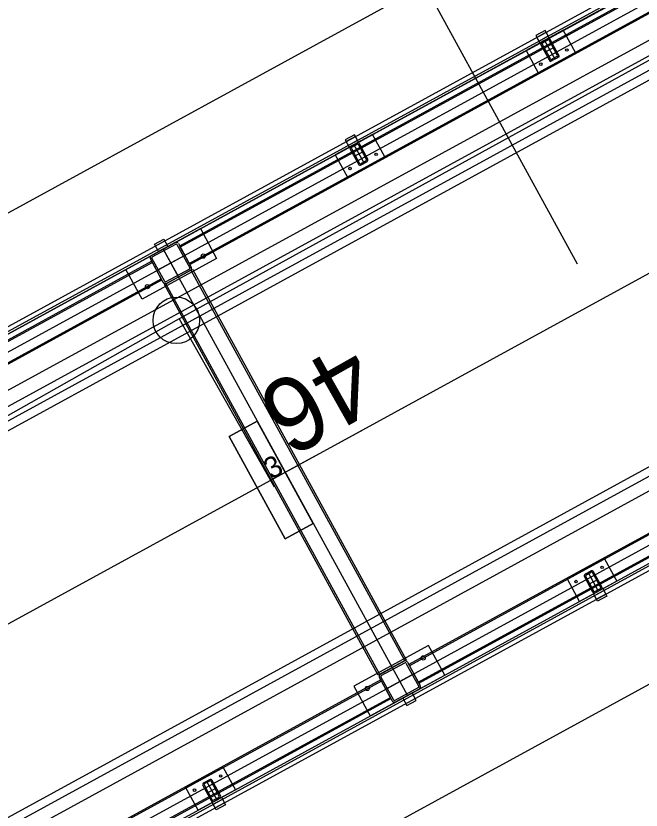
# Model space of a CAD drawing. Extents: x -783978 to -783565, y -1064821 to -1064596.
# Drawn here: x -783784.57 to -783781.623, y -1064693.706 to -1064689.961 of the extents above; entities that cross this region are included whole.
import ezdxf

# ---------------------------------------------------------------- set-up
doc = ezdxf.new("R2010")
doc.units = 0
for name, color, linetype in [('Default', 7, 'Continuous'), ('SO 01_20_01', 7, 'Continuous'), ('SO 01_50_01', 7, 'Continuous'), ('SO 01_74_01', 7, 'Continuous'), ('SO 01_86_04', 7, 'Continuous')]:
    doc.layers.add(name, color=color, linetype=linetype)

# ---------------------------------------------------------------- blocks, each defined once
blk = doc.blocks.new('POINT_DISPLAY')
at = {"layer": 'Default'}
blk.add_line((0, 0), (0, 0), dxfattribs=at)

msp = doc.modelspace()

# ---------------------------------------------------------------- linework, layer by layer
at = {"layer": 'SO 01_20_01'}
for p, q in [((-783735.0054, -1064663.7532), (-783787.4671, -1064692.4555)), ((-783735.2041, -1064664.4318), (-783786.7885, -1064692.6541)), ((-783786.6445, -1064692.9173), (-783735.3233, -1064664.839)), ((-783738.0171, -1064666.3812), (-783786.4402, -1064692.874)), ((-783786.421, -1064692.9091), (-783737.9979, -1064666.4163)), ((-783737.8741, -1064667.2605), (-783785.3352, -1064693.2269)), ((-783785.6531, -1064694.3127), (-783737.23, -1064667.82)), ((-783737.0912, -1064667.858), (-783785.7805, -1064694.4964)), ((-783737.2108, -1064667.855), (-783785.6339, -1064694.3478)), ((-783785.6366, -1064694.7596), (-783736.9472, -1064668.1212)), ((-783746.2961, -1064673.8055), (-783785.8354, -1064695.4379))]:
    msp.add_line(p, q, dxfattribs=at)
at = {"layer": 'SO 01_50_01'}
for p, q in [((-783786.7885, -1064692.6541), (-783725.4827, -1064659.1131)), ((-783782.4021, -1064690.2543), (-783778.0156, -1064687.8544)), ((-783782.402, -1064690.2544), (-783778.0156, -1064687.8545)), ((-783782.402, -1064690.2544), (-783778.0156, -1064687.8545)), ((-783781.9221, -1064691.1316), (-783782.882, -1064689.377)), ((-783786.7885, -1064692.6541), (-783782.4021, -1064690.2543)), ((-783786.7884, -1064692.6542), (-783782.402, -1064690.2544)), ((-783786.7884, -1064692.6542), (-783782.402, -1064690.2544))]:
    msp.add_line(p, q, dxfattribs=at)
at = {"layer": 'SO 01_74_01'}
for p, q in [((-783735.2185, -1064664.4055), (-783786.6099, -1064692.5222)), ((-783786.6003, -1064692.5398), (-783735.2089, -1064664.423)), ((-783785.4388, -1064694.6628), (-783745.8293, -1064672.9921)), ((-783745.8197, -1064673.0096), (-783785.4292, -1064694.6803)), ((-783781.232, -1064689.6427), (-783783.7981, -1064691.0466)), ((-783781.229, -1064689.6482), (-783783.7951, -1064691.0521)), ((-783783.7531, -1064691.1288), (-783781.1871, -1064689.7249)), ((-783783.7501, -1064691.1343), (-783781.1841, -1064689.7304)), ((-783782.0747, -1064690.0296), (-783782.1186, -1064690.0536)), ((-783782.0555, -1064690.0647), (-783782.0747, -1064690.0296)), ((-783782.1186, -1064690.0536), (-783782.0994, -1064690.0887)), ((-783782.0699, -1064690.0384), (-783782.1138, -1064690.0624)), ((-783782.1138, -1064690.0624), (-783782.1042, -1064690.0799)), ((-783782.1042, -1064690.0799), (-783782.0603, -1064690.0559)), ((-783782.0994, -1064690.0887), (-783782.0555, -1064690.0647)), ((-783782.0603, -1064690.0559), (-783782.0699, -1064690.0384)), ((-783782.974, -1064690.5216), (-783783.0178, -1064690.5456)), ((-783782.9548, -1064690.5567), (-783782.974, -1064690.5216)), ((-783783.0178, -1064690.5456), (-783782.9986, -1064690.5807)), ((-783782.9692, -1064690.5303), (-783783.013, -1064690.5543)), ((-783783.013, -1064690.5543), (-783783.0034, -1064690.5719)), ((-783783.0034, -1064690.5719), (-783782.9596, -1064690.5479)), ((-783782.9986, -1064690.5807), (-783782.9548, -1064690.5567)), ((-783782.9596, -1064690.5479), (-783782.9692, -1064690.5303)), ((-783783.917, -1064691.0375), (-783783.8732, -1064691.0135)), ((-783783.8978, -1064691.0726), (-783783.917, -1064691.0375)), ((-783783.8732, -1064691.0135), (-783783.854, -1064691.0486)), ((-783783.7981, -1064691.0466), (-783783.7501, -1064691.1343)), ((-783783.854, -1064691.0486), (-783783.8978, -1064691.0726)), ((-783783.7951, -1064691.0521), (-783783.7531, -1064691.1288)), ((-783783.9297, -1064691.1186), (-783786.4958, -1064692.5225)), ((-783783.8817, -1064691.2063), (-783783.9297, -1064691.1186)), ((-783783.9267, -1064691.1241), (-783786.4927, -1064692.528)), ((-783783.8847, -1064691.2008), (-783783.9267, -1064691.1241)), ((-783783.8697, -1064691.2282), (-783783.7381, -1064691.1562)), ((-783783.7381, -1064691.1562), (-783782.7302, -1064692.9985)), ((-783783.8627, -1064691.2244), (-783783.7451, -1064691.1601)), ((-783783.7451, -1064691.1601), (-783782.7372, -1064693.0024)), ((-783786.4508, -1064692.6047), (-783783.8847, -1064691.2008)), ((-783786.4478, -1064692.6102), (-783783.8817, -1064691.2063)), ((-783782.8618, -1064693.0705), (-783783.8697, -1064691.2282)), ((-783782.8547, -1064693.0667), (-783783.8627, -1064691.2244)), ((-783780.1521, -1064691.6165), (-783782.7182, -1064693.0205)), ((-783780.1491, -1064691.6221), (-783782.7151, -1064693.026)), ((-783782.6732, -1064693.1027), (-783780.1071, -1064691.6987)), ((-783782.6702, -1064693.1082), (-783780.1041, -1064691.7043)), ((-783781.8467, -1064692.6861), (-783781.8028, -1064692.6621)), ((-783781.8275, -1064692.7212), (-783781.8467, -1064692.6861)), ((-783781.8419, -1064692.6949), (-783781.798, -1064692.6709)), ((-783781.7884, -1064692.6885), (-783781.8323, -1064692.7125)), ((-783781.8028, -1064692.6621), (-783781.7836, -1064692.6972)), ((-783781.798, -1064692.6709), (-783781.7884, -1064692.6885)), ((-783781.8323, -1064692.7125), (-783781.8419, -1064692.6949)), ((-783781.7836, -1064692.6972), (-783781.8275, -1064692.7212)), ((-783782.7302, -1064692.9985), (-783782.8618, -1064693.0705)), ((-783782.7372, -1064693.0024), (-783782.8547, -1064693.0667)), ((-783782.7182, -1064693.0205), (-783782.6702, -1064693.1082)), ((-783782.7151, -1064693.026), (-783782.6732, -1064693.1027)), ((-783782.8498, -1064693.0925), (-783785.4158, -1064694.4964)), ((-783782.8467, -1064693.098), (-783785.4128, -1064694.5019)), ((-783782.8018, -1064693.1802), (-783782.8498, -1064693.0925)), ((-783782.8048, -1064693.1747), (-783782.8467, -1064693.098)), ((-783785.3708, -1064694.5786), (-783782.8048, -1064693.1747)), ((-783785.3678, -1064694.5841), (-783782.8018, -1064693.1802)), ((-783782.702, -1064693.1541), (-783782.7459, -1064693.1781)), ((-783782.7459, -1064693.1781), (-783782.7267, -1064693.2132)), ((-783782.6828, -1064693.1892), (-783782.702, -1064693.1541)), ((-783782.7267, -1064693.2132), (-783782.6828, -1064693.1892)), ((-783783.6451, -1064693.6701), (-783783.6013, -1064693.6461)), ((-783783.6403, -1064693.6789), (-783783.5965, -1064693.6549)), ((-783783.6013, -1064693.6461), (-783783.5821, -1064693.6812)), ((-783783.5965, -1064693.6549), (-783783.5869, -1064693.6724)), ((-783783.6259, -1064693.7052), (-783783.6451, -1064693.6701)), ((-783783.6307, -1064693.6964), (-783783.6403, -1064693.6789)), ((-783783.5869, -1064693.6724), (-783783.6307, -1064693.6964)), ((-783783.5821, -1064693.6812), (-783783.6259, -1064693.7052))]:
    msp.add_line(p, q, dxfattribs=at)
for points in [[(-783735.1681, -1064664.4976), (-783787.4762, -1064693.1159)], [(-783734.0882, -1064666.4715), (-783786.3963, -1064695.0898)], [(-783782.0638, -1064690.0692), (-783782.0911, -1064690.0842)], [(-783782.0949, -1064690.097), (-783782.0559, -1064690.1681)], [(-783782.0893, -1064690.094), (-783782.0504, -1064690.1651)], [(-783782.0608, -1064690.0748), (-783782.0881, -1064690.0897)], [(-783782.0775, -1064690.0767), (-783782.0295, -1064690.1644)], [(-783782.0315, -1064690.1086), (-783782.0754, -1064690.1326)], [(-783782.0176, -1064690.1472), (-783782.0565, -1064690.076)], [(-783782.0121, -1064690.1441), (-783782.051, -1064690.073)], [(-783782.0461, -1064690.1664), (-783782.0189, -1064690.1514)], [(-783782.0431, -1064690.1719), (-783782.0158, -1064690.157)], [(-783782.9941, -1064690.589), (-783782.9552, -1064690.6601)], [(-783782.963, -1064690.5612), (-783782.9903, -1064690.5761)], [(-783782.9886, -1064690.5859), (-783782.9496, -1064690.6571)], [(-783782.96, -1064690.5667), (-783782.9873, -1064690.5817)], [(-783782.9767, -1064690.5687), (-783782.9287, -1064690.6564)], [(-783782.9168, -1064690.6391), (-783782.9557, -1064690.568)], [(-783782.9113, -1064690.6361), (-783782.9502, -1064690.565)], [(-783782.9308, -1064690.6005), (-783782.9746, -1064690.6245)], [(-783782.9454, -1064690.6583), (-783782.9181, -1064690.6434)], [(-783782.9423, -1064690.6639), (-783782.915, -1064690.6489)], [(-783783.9312, -1064691.0909), (-783783.8206, -1064691.0304)], [(-783783.9273, -1064691.0979), (-783783.8168, -1064691.0374)], [(-783783.8114, -1064691.039), (-783783.7509, -1064691.1495)], [(-783783.8043, -1064691.0352), (-783783.7439, -1064691.1457)], [(-783783.8759, -1064691.0606), (-783782.724, -1064693.1661)], [(-783783.8759, -1064691.0606), (-783783.8039, -1064691.1922)], [(-783783.8755, -1064691.2177), (-783783.9359, -1064691.1072)], [(-783783.8684, -1064691.2139), (-783783.9289, -1064691.1033)], [(-783783.7741, -1064691.0904), (-783783.9057, -1064691.1624)], [(-783783.7525, -1064691.155), (-783783.863, -1064691.2154)], [(-783783.7486, -1064691.162), (-783783.8592, -1064691.2225)], [(-783781.8591, -1064692.579), (-783781.8864, -1064692.5939)], [(-783781.8901, -1064692.6067), (-783781.8512, -1064692.6779)], [(-783781.8846, -1064692.6037), (-783781.8457, -1064692.6748)], [(-783781.8561, -1064692.5845), (-783781.8834, -1064692.5994)], [(-783781.8728, -1064692.5864), (-783781.8248, -1064692.6741)], [(-783781.8268, -1064692.6183), (-783781.8707, -1064692.6423)], [(-783781.8129, -1064692.6569), (-783781.8518, -1064692.5857)], [(-783781.8074, -1064692.6539), (-783781.8463, -1064692.5827)], [(-783781.8414, -1064692.6761), (-783781.8141, -1064692.6612)], [(-783781.8384, -1064692.6816), (-783781.8111, -1064692.6667)], [(-783782.8512, -1064693.0648), (-783782.7407, -1064693.0043)], [(-783782.8474, -1064693.0718), (-783782.7369, -1064693.0113)], [(-783782.7314, -1064693.0129), (-783782.671, -1064693.1234)], [(-783782.7244, -1064693.0091), (-783782.6639, -1064693.1196)], [(-783782.6942, -1064693.0643), (-783782.8258, -1064693.1363)], [(-783782.796, -1064693.0345), (-783782.724, -1064693.1661)], [(-783782.7955, -1064693.1916), (-783782.856, -1064693.081)], [(-783782.7885, -1064693.1877), (-783782.849, -1064693.0772)], [(-783782.6725, -1064693.1289), (-783782.7831, -1064693.1893)], [(-783782.6687, -1064693.1359), (-783782.7792, -1064693.1964)], [(-783783.6886, -1064693.5906), (-783783.6497, -1064693.6618)], [(-783783.6575, -1064693.5629), (-783783.6848, -1064693.5778)], [(-783783.6831, -1064693.5876), (-783783.6441, -1064693.6588)], [(-783783.6545, -1064693.5684), (-783783.6818, -1064693.5833)], [(-783783.6712, -1064693.5704), (-783783.6232, -1064693.6581)], [(-783783.6113, -1064693.6408), (-783783.6502, -1064693.5697)], [(-783783.6058, -1064693.6378), (-783783.6447, -1064693.5666)], [(-783783.6253, -1064693.6022), (-783783.6691, -1064693.6262)], [(-783783.6399, -1064693.66), (-783783.6126, -1064693.6451)], [(-783783.6368, -1064693.6655), (-783783.6095, -1064693.6506)]]:
    msp.add_lwpolyline(points, dxfattribs=at)
for points in [[(-783781.9897, -1064690.0287), (-783782.1652, -1064690.1247), (-783782.1076, -1064690.23), (-783781.9321, -1064690.134)], [(-783782.0555, -1064690.0647), (-783782.0994, -1064690.0887), (-783782.0514, -1064690.1764), (-783782.0075, -1064690.1524)], [(-783782.889, -1064690.5207), (-783783.0644, -1064690.6167), (-783783.0068, -1064690.7219), (-783782.8314, -1064690.6259)], [(-783783.6237, -1064691.105), (-783783.9746, -1064691.297), (-783784.0514, -1064691.1566), (-783783.7004, -1064690.9646)], [(-783781.737, -1064692.6261), (-783781.9125, -1064692.7221), (-783781.9701, -1064692.6169), (-783781.7946, -1064692.5209)], [(-783782.6253, -1064692.9298), (-783782.9762, -1064693.1217), (-783782.8994, -1064693.2621), (-783782.5485, -1064693.0701)], [(-783783.5355, -1064693.6101), (-783783.7109, -1064693.7061), (-783783.7685, -1064693.6008), (-783783.5931, -1064693.5048)]]:
    msp.add_lwpolyline(points, close=True, dxfattribs=at)
for centre, radius in [((-783781.9729, -1064690.1221), 0.006), ((-783782.0957, -1064690.1892), 0.006), ((-783782.8721, -1064690.614), 0.006), ((-783782.9949, -1064690.6812), 0.006), ((-783783.6867, -1064691.0939), 0.01), ((-783783.9499, -1064691.2379), 0.01), ((-783781.8065, -1064692.5616), 0.006), ((-783781.9294, -1064692.6288), 0.006), ((-783782.65, -1064692.9888), 0.01), ((-783782.9132, -1064693.1328), 0.01), ((-783783.605, -1064693.5455), 0.006), ((-783783.7278, -1064693.6127), 0.006)]:
    msp.add_circle(centre, radius, dxfattribs=at)
for centre, radius, start, end in [((-783782.0593, -1064690.0775), 0.00945, 28.6835, 118.6835), ((-783782.0866, -1064690.0924), 0.00945, 118.6835, 208.6835), ((-783782.0866, -1064690.0924), 0.00315, 118.6835, 208.6835), ((-783782.0593, -1064690.0775), 0.00315, 28.6835, 118.6835), ((-783782.0204, -1064690.1487), 0.00315, 298.6835, 28.6835), ((-783782.0204, -1064690.1487), 0.00945, 298.6835, 28.6835), ((-783782.0476, -1064690.1636), 0.00945, 208.6835, 298.6835), ((-783782.0476, -1064690.1636), 0.00315, 208.6835, 298.6835), ((-783782.9858, -1064690.5844), 0.00945, 118.6835, 208.6835), ((-783782.9858, -1064690.5844), 0.00315, 118.6835, 208.6835), ((-783782.9585, -1064690.5695), 0.00945, 28.6835, 118.6835), ((-783782.9585, -1064690.5695), 0.00315, 28.6835, 118.6835), ((-783782.9469, -1064690.6556), 0.00945, 208.6835, 298.6835), ((-783782.9469, -1064690.6556), 0.00315, 208.6835, 298.6835), ((-783782.9196, -1064690.6406), 0.00315, 298.6835, 28.6835), ((-783782.9196, -1064690.6406), 0.00945, 298.6835, 28.6835), ((-783783.8149, -1064691.0409), 0.012, 28.6835, 118.6835), ((-783783.8149, -1064691.0409), 0.004, 28.6835, 118.6835), ((-783783.9254, -1064691.1014), 0.012, 118.6835, 208.6835), ((-783783.9254, -1064691.1014), 0.004, 118.6835, 208.6835), ((-783783.7544, -1064691.1515), 0.004, 298.6835, 28.6835), ((-783783.7544, -1064691.1515), 0.012, 298.6835, 28.6835), ((-783783.8649, -1064691.2119), 0.012, 208.6835, 298.6835), ((-783783.8649, -1064691.2119), 0.004, 208.6835, 298.6835), ((-783781.8546, -1064692.5872), 0.00945, 28.6835, 118.6835), ((-783781.8819, -1064692.6022), 0.00945, 118.6835, 208.6835), ((-783781.8819, -1064692.6022), 0.00315, 118.6835, 208.6835), ((-783781.8546, -1064692.5872), 0.00315, 28.6835, 118.6835), ((-783781.8157, -1064692.6584), 0.00315, 298.6835, 28.6835), ((-783781.8157, -1064692.6584), 0.00945, 298.6835, 28.6835), ((-783781.8429, -1064692.6733), 0.00945, 208.6835, 298.6835), ((-783781.8429, -1064692.6733), 0.00315, 208.6835, 298.6835), ((-783782.7349, -1064693.0148), 0.012, 28.6835, 118.6835), ((-783782.7349, -1064693.0148), 0.004, 28.6835, 118.6835), ((-783782.8455, -1064693.0753), 0.012, 118.6835, 208.6835), ((-783782.8455, -1064693.0753), 0.004, 118.6835, 208.6835), ((-783782.6745, -1064693.1254), 0.004, 298.6835, 28.6835), ((-783782.6745, -1064693.1254), 0.012, 298.6835, 28.6835), ((-783782.785, -1064693.1858), 0.012, 208.6835, 298.6835), ((-783782.785, -1064693.1858), 0.004, 208.6835, 298.6835), ((-783783.6803, -1064693.5861), 0.00945, 118.6835, 208.6835), ((-783783.6803, -1064693.5861), 0.00315, 118.6835, 208.6835), ((-783783.653, -1064693.5712), 0.00945, 28.6835, 118.6835), ((-783783.653, -1064693.5712), 0.00315, 28.6835, 118.6835), ((-783783.6414, -1064693.6573), 0.00945, 208.6835, 298.6835), ((-783783.6414, -1064693.6573), 0.00315, 208.6835, 298.6835), ((-783783.6141, -1064693.6423), 0.00315, 298.6835, 28.6835), ((-783783.6141, -1064693.6423), 0.00945, 298.6835, 28.6835)]:
    msp.add_arc(centre, radius, start, end, dxfattribs=at)
at = {"layer": 'SO 01_86_04'}
for p, q in [((-783783.8002, -1064691.3894), (-783783.3522, -1064692.1825)), ((-783783.4325, -1064691.8722), (-783783.5641, -1064691.9442)), ((-783783.4325, -1064691.8722), (-783783.5641, -1064691.9442)), ((-783783.5641, -1064691.9442), (-783783.4325, -1064691.8722)), ((-783783.5641, -1064691.9442), (-783783.4325, -1064691.8722)), ((-783783.1685, -1064692.3547), (-783783.4325, -1064691.8722)), ((-783783.1685, -1064692.3547), (-783783.4325, -1064691.8722)), ((-783783.4325, -1064691.8722), (-783783.1685, -1064692.3547)), ((-783783.4325, -1064691.8722), (-783783.1685, -1064692.3547)), ((-783783.5641, -1064691.9442), (-783783.3001, -1064692.4267)), ((-783783.5641, -1064691.9442), (-783783.3001, -1064692.4267)), ((-783783.3001, -1064692.4267), (-783783.5641, -1064691.9442)), ((-783783.3001, -1064692.4267), (-783783.5641, -1064691.9442)), ((-783783.3663, -1064692.1494), (-783782.9276, -1064691.9094)), ((-783783.3001, -1064692.4267), (-783783.1685, -1064692.3547)), ((-783783.3001, -1064692.4267), (-783783.1685, -1064692.3547)), ((-783783.1685, -1064692.3547), (-783783.3001, -1064692.4267)), ((-783783.1685, -1064692.3547), (-783783.3001, -1064692.4267))]:
    msp.add_line(p, q, dxfattribs=at)
for points in [[(-783738.3222, -1064666.4797), (-783740.5325, -1064667.689), (-783743.1715, -1064669.1328), (-783745.7538, -1064670.5456), (-783748.4385, -1064672.0145), (-783751.0413, -1064673.4385), (-783753.6847, -1064674.8847), (-783756.3281, -1064676.3309), (-783758.9715, -1064677.7772), (-783761.6149, -1064679.2234), (-783764.2583, -1064680.6696), (-783766.9018, -1064682.1159), (-783769.4633, -1064683.5173), (-783772.109, -1064684.9648), (-783774.7882, -1064686.4306), (-783778.1382, -1064688.2722), (-783783.8139, -1064691.3971), (-783785.747, -1064692.4898)], [(-783747.063, -1064670.9765), (-783746.9575, -1064671.1681), (-783786.6893, -1064692.8619), (-783786.185, -1064693.7636)]]:
    msp.add_lwpolyline(points, dxfattribs=at)
msp.add_circle((-783783.8139, -1064691.3971), 0.1097, dxfattribs=at)

# ---------------------------------------------------------------- block references
at = {"layer": 'SO 01_86_04', "xscale": 0.010000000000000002, "yscale": 0.009999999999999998, "rotation": 28.683491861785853}
for p in [(-783783.4325, -1064691.8722), (-783783.4325, -1064691.8722), (-783783.5641, -1064691.9442), (-783783.5641, -1064691.9442), (-783783.1685, -1064692.3547), (-783783.1685, -1064692.3547), (-783783.3001, -1064692.4267), (-783783.3001, -1064692.4267)]:
    msp.add_blockref('POINT_DISPLAY', p, dxfattribs=at)

# ---------------------------------------------------------------- texts
at = {"layer": 'SO 01_86_04'}
for s, height, rotation, p in [('46', 0.351, 209.46, (-783782.9971, -1064691.4873)), ('3', 0.1, 28.6835, (-783783.3663, -1064692.1494))]:
    msp.add_text(s, height=height, rotation=rotation, dxfattribs=at).set_placement(p)

doc.saveas('drawing.dxf')
